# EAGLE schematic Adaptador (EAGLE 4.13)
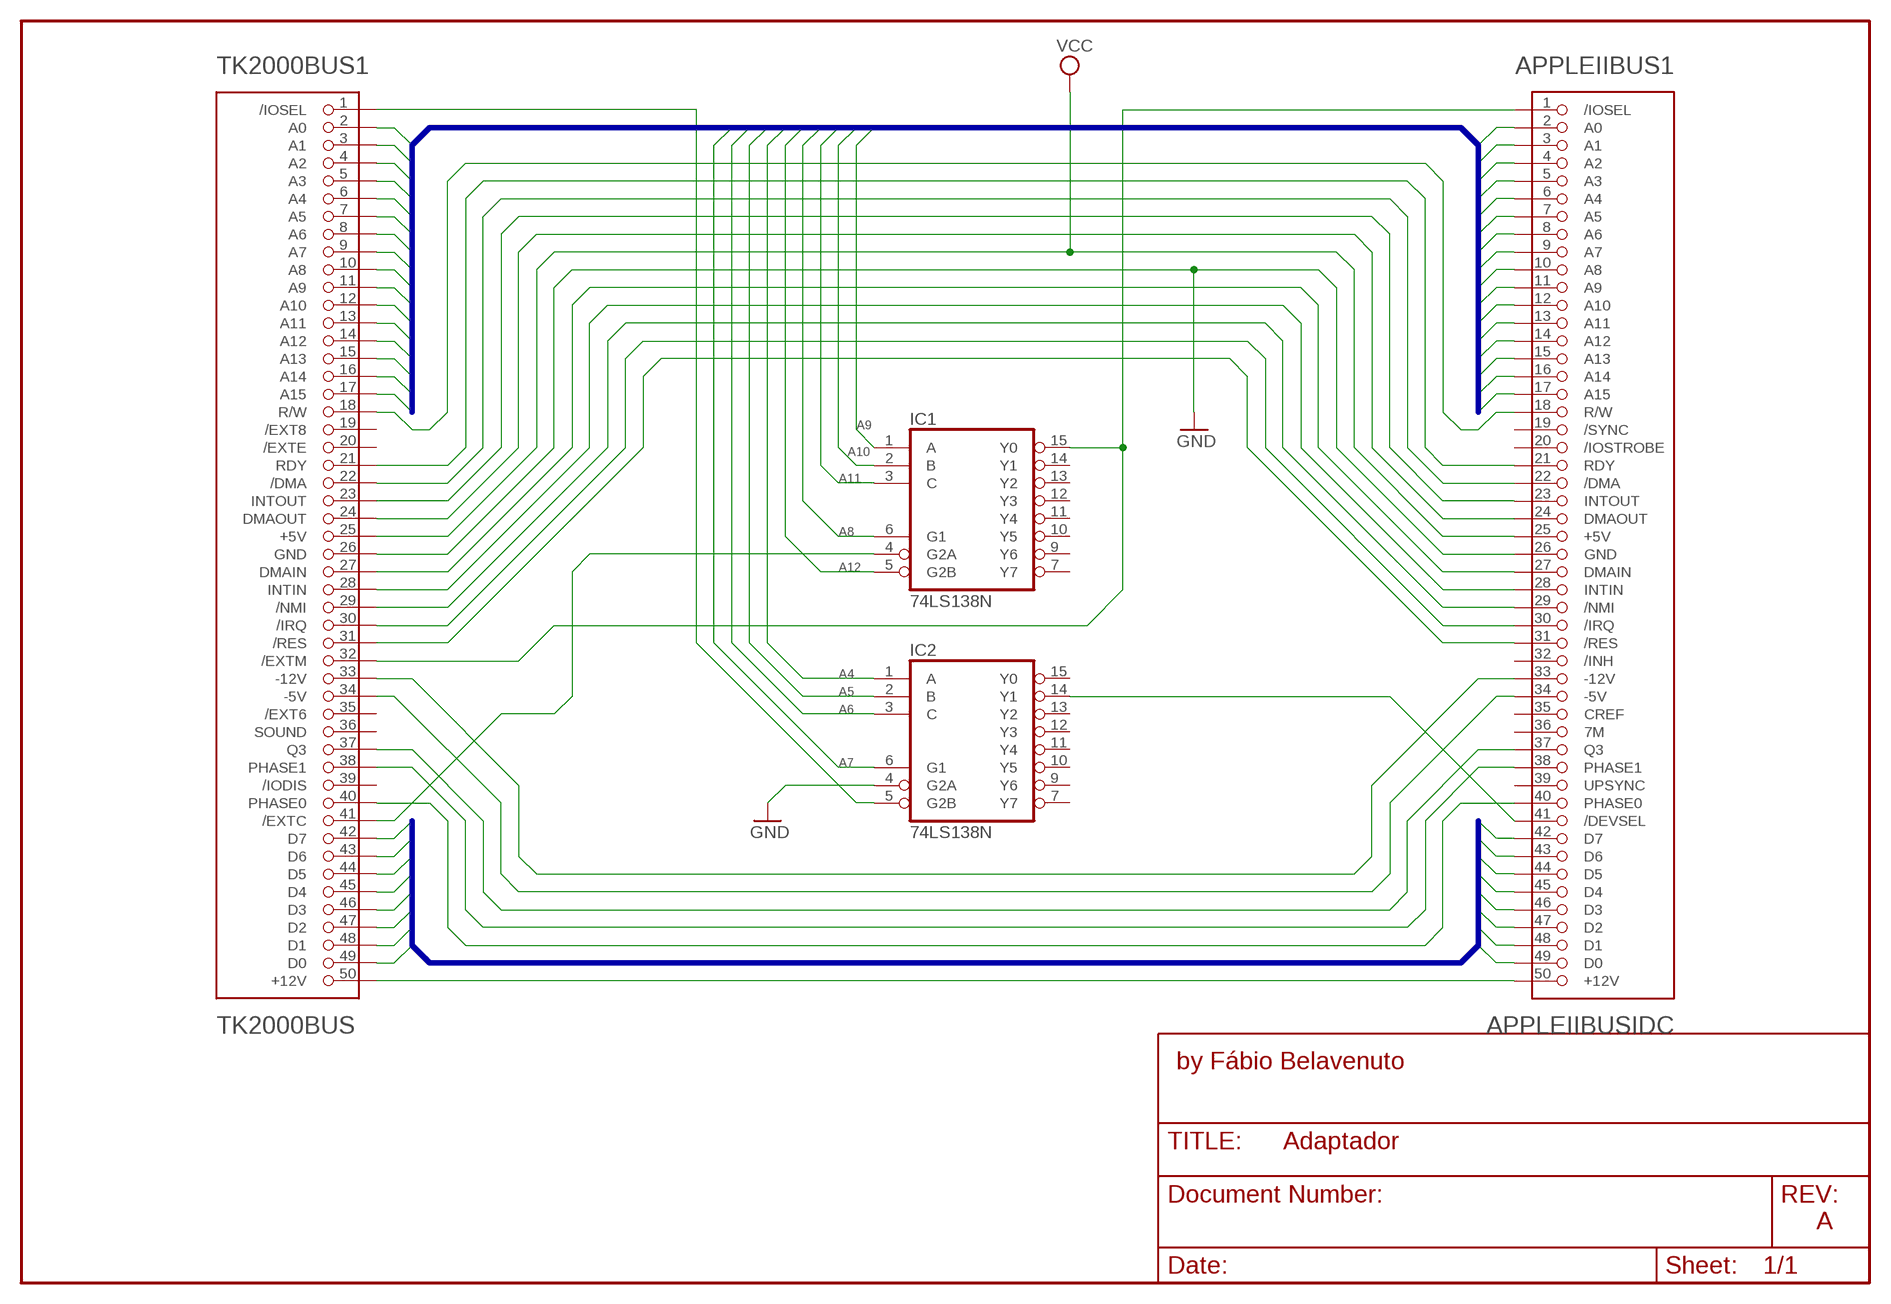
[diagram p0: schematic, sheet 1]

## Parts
APPLEIIBUS1  APPLEIIBUSIDC  [CONECTORIDC]
IC1  74LS138N  [DIL16]
IC2  74LS138N  [DIL16]
TK2000BUS1  TK2000BUS  [CONECTORBUS]

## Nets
+12V: APPLEIIBUS1.50(+12V) TK2000BUS1.50(+12V)
/DMA: APPLEIIBUS1.22(/DMA) TK2000BUS1.22(/DMA)
A0: APPLEIIBUS1.2(A0) TK2000BUS1.2(A0)
A1: APPLEIIBUS1.3(A1) TK2000BUS1.3(A1)
A2: APPLEIIBUS1.4(A2) TK2000BUS1.4(A2)
A3: APPLEIIBUS1.5(A3) TK2000BUS1.5(A3)
A4: APPLEIIBUS1.6(A4) IC2.1(A) TK2000BUS1.6(A4)
A5: APPLEIIBUS1.7(A5) IC2.2(B) TK2000BUS1.7(A5)
A6: APPLEIIBUS1.8(A6) IC2.3(C) TK2000BUS1.8(A6)
A7: APPLEIIBUS1.9(A7) IC2.6(G1) TK2000BUS1.9(A7)
A8: APPLEIIBUS1.10(A8) IC1.6(G1) TK2000BUS1.10(A8)
A9: APPLEIIBUS1.11(A9) IC1.1(A) TK2000BUS1.11(A9)
A10: APPLEIIBUS1.12(A10) IC1.2(B) TK2000BUS1.12(A10)
A11: APPLEIIBUS1.13(A11) IC1.3(C) TK2000BUS1.13(A11)
A12: APPLEIIBUS1.14(A12) IC1.5(G2B) TK2000BUS1.14(A12)
A13: APPLEIIBUS1.15(A13) TK2000BUS1.15(A13)
A14: APPLEIIBUS1.16(A14) TK2000BUS1.16(A14)
A15: APPLEIIBUS1.17(A15) TK2000BUS1.17(A15)
D0: APPLEIIBUS1.49(D0) TK2000BUS1.49(D0)
D1: APPLEIIBUS1.48(D1) TK2000BUS1.48(D1)
D2: APPLEIIBUS1.47(D2) TK2000BUS1.47(D2)
D3: APPLEIIBUS1.46(D3) TK2000BUS1.46(D3)
D4: APPLEIIBUS1.45(D4) TK2000BUS1.45(D4)
D5: APPLEIIBUS1.44(D5) TK2000BUS1.44(D5)
D6: APPLEIIBUS1.43(D6) TK2000BUS1.43(D6)
D7: APPLEIIBUS1.42(D7) TK2000BUS1.42(D7)
GND: APPLEIIBUS1.26(GND) IC2.4(G2A) TK2000BUS1.26(GND)
N$1: APPLEIIBUS1.40(PHASE0) TK2000BUS1.40(PHASE0)
N$2: APPLEIIBUS1.38(PHASE1) TK2000BUS1.38(PHASE1)
N$3: APPLEIIBUS1.23(INTOUT) TK2000BUS1.23(INTOUT)
N$4: APPLEIIBUS1.24(DMAOUT) TK2000BUS1.24(DMAOUT)
N$5: APPLEIIBUS1.41(/DEVSEL) IC2.14(Y1)
N$7: APPLEIIBUS1.27(DMAIN) TK2000BUS1.27(DMAIN)
N$8: APPLEIIBUS1.28(INTIN) TK2000BUS1.28(INTIN)
N$9: APPLEIIBUS1.29(/NMI) TK2000BUS1.29(/NMI)
N$10: APPLEIIBUS1.30(/IRQ) TK2000BUS1.30(/IRQ)
N$11: APPLEIIBUS1.31(/RES) TK2000BUS1.31(/RES)
N$12: APPLEIIBUS1.33(-12V) TK2000BUS1.33(-12V)
N$13: APPLEIIBUS1.34(-5V) TK2000BUS1.34(-5V)
N$14: APPLEIIBUS1.37(Q3) TK2000BUS1.37(Q3)
N$15: IC1.4(G2A) TK2000BUS1.41(/EXTC)
N$16: APPLEIIBUS1.1(/IOSEL) IC1.15(Y0) TK2000BUS1.32(/EXTM)
N$17: IC2.5(G2B) TK2000BUS1.1(/IOSEL)
R/W: APPLEIIBUS1.18(R/W) TK2000BUS1.18(R/W)
RDY: APPLEIIBUS1.21(RDY) TK2000BUS1.21(RDY)
VCC: APPLEIIBUS1.25(+5V) TK2000BUS1.25(+5V)
Unconnected: APPLEIIBUS1.19(/SYNC) APPLEIIBUS1.20(/IOSTROBE) APPLEIIBUS1.32(/INH) APPLEIIBUS1.35(CREF) APPLEIIBUS1.36(7M) APPLEIIBUS1.39(UPSYNC) IC1.7(Y7) IC1.9(Y6) IC1.10(Y5) IC1.11(Y4) IC1.12(Y3) IC1.13(Y2) IC1.14(Y1) IC2.7(Y7) IC2.9(Y6) IC2.10(Y5) IC2.11(Y4) IC2.12(Y3) IC2.13(Y2) IC2.15(Y0) TK2000BUS1.19(/EXT8) TK2000BUS1.20(/EXTE) TK2000BUS1.35(/EXT6) TK2000BUS1.36(SOUND) TK2000BUS1.39(/IODIS)

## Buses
A[0..15]
D[0..7]

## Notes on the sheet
- by Fábio Belavenuto
- A

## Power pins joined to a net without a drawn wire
GND: IC1.8(GND) IC2.8(GND)
VCC: IC1.16(VCC) IC2.16(VCC)

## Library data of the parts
APPLEIIBUS1 = AppleII:APPLEIIBUS: BUS do Apple II
IC1 IC2 = 74xx-us:74*138: 3-line to 8-line DECODER/DEMULTIPLEXER
TK2000BUS1 = ConectorTK2000:TK2000BUS: BUS do TK2000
